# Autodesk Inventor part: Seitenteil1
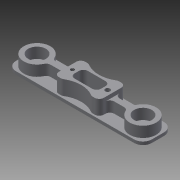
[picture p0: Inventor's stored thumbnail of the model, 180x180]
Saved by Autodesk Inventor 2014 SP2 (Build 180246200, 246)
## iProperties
Created: 2015-04
Part Number: Seitenteil1
Material: Generisch
Document SubType Name: Modeling
Designer: e_krauts
Density: 1 g/cm^3
Appearance: Vorgabe
Mass: 43.9559 g
Surface Area: 202.761 cm^2
Volume: 43.9559 cm^3
Author: e_krauts
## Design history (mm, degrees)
sketch "Skizze1"
  geometry: L1 (0, 0)-(154, 0); L2 (154, 0)-(154, 34); L3 (154, 34)-(0, 34); L4 (0, 34)-(0, 0)
  constraints: 8 end point, 2 parallel, 1 horizontal, 1 perpendicular
  dimensions: "d0" = 154 distance of L3.end L2.end; "d1" = 34 distance between parallel lines of L3 L1
extrude "Extrusion1" new body sketch "Skizze1" distance "d2" = 3.5; taper "d3" = 0 deg
sketch "Skizze2"
  geometry: L1 (0, 0)-(154, 0) reference; L2 (154, 0)-(154, 34) reference; L3 (154, 34)-(0, 34) reference; L4 (0, 34)-(0, 0) reference; L5 (77, 34)-(77, 0); L6 (0, 17)-(154, 17); L7 (77, 20)-(35.33, 20); L8 (77, 14)-(35.33, 14); L9 (77, 20)-(118.67, 20); L10 (77, 14)-(118.67, 14); L11 (154, 17)-(0, 17); A1 r 5 centre (35.33, 25) between (30.748, 23) and (35.33, 20); A2 r 15 centre (17, 17) between (30.748, 23) and (2, 17); A3 r 5 centre (35.33, 9) between (35.33, 14) and (30.748, 11); A4 r 15 centre (17, 17) between (2, 17) and (30.748, 11); A5 r 5 centre (118.67, 25) between (118.67, 20) and (123.252, 23); A6 r 15 centre (137, 17) between (123.252, 11) and (152, 17); A7 r 15 centre (137, 17) between (152, 17) and (123.252, 23); A8 r 5 centre (118.67, 9) between (123.252, 11) and (118.67, 14)
  constraints: 16 point on circle, 14 end point, 14 symmetric about line, 8 centre point, 5 point on line, 4 midpoint, 2 tangent, 1 parallel, 6 other
  dimensions: "d4" = 6 diameter of L7 L6; "d5" = 15 radius of A2; "d6" = 120 diameter of A2.centre L5; "d7" = 5 radius of A1
extrude "Extrusion2" join sketch "Skizze2" distance "d8" = 12; taper "d9" = 0 deg
sketch "Skizze3"
  geometry: A1 r 15 centre (17, 17) between (30.748, 23) and (30.748, 11) reference; A2 r 15 centre (137, 17) between (123.252, 11) and (123.252, 23) reference; 3 further points
  constraints: 2 coincident
hole "Bohrung1" sketch "Skizze3" at (17, 17), (137, 17) diameter "d10" = 20; stored, may be unused: countersink angle "d14" = 90 deg, drill point angle "d16" = 0 deg; dims "d11" = 6, "d12" = 4, "d13" = 2, "d15" = 12
fillet "Rundung1" dims "d17" = 10
sketch "Skizze4"
  geometry: L1 (144, 34)-(10, 34) reference; L2 (0, 24)-(0, 10) reference; L3 (10, 0)-(144, 0) reference; L4 (154, 10)-(154, 24) reference; L5 (77, 34)-(77, 0); L6 (0, 17)-(154, 17); L7 (102.5, 32)-(51.5, 32); L8 (51.5, 32)-(51.5, 2); L9 (51.5, 2)-(102.5, 2); L10 (102.5, 2)-(102.5, 32); L11 (102.5, 32)-(51.5, 2); L12 (51.5, 32)-(102.5, 2); 2 further points
  constraints: 16 end point, 7 midpoint, 2 parallel, 1 horizontal, 1 perpendicular
  dimensions: "d18" = 51 distance of L9.end L8.end; "d19" = 30 distance of L8.end L7.end
extrude "Extrusion3" join sketch "Skizze4" distance "d20" = 16.5; taper "d21" = 0 deg
fillet "Rundung2" dims "d22" = 5
sketch "Skizze5"
  geometry: L1 (62, 24.5)-(92, 24.5); L2 (92, 24.5)-(92, 9.5); L3 (92, 9.5)-(62, 9.5); L4 (62, 9.5)-(62, 24.5); L5 (62, 24.5)-(92, 9.5); L6 (92, 24.5)-(62, 9.5); 2 further points
  constraints: 12 end point, 2 midpoint, 2 parallel, 1 horizontal, 1 perpendicular
  dimensions: "d23" = 30 distance of L2.end L3.end; "d24" = 15 distance of L1.end L2.end
extrude "Extrusion4" cut sketch "Skizze5" distance "d25" = 16.5; taper "d26" = 0 deg
fillet "Rundung3" dims "d27" = 5
sketch "Skizze6"
  geometry: L1 (51.5, 27)-(51.5, 7) reference; L2 (56.5, 2)-(97.5, 2) reference; L3 (102.5, 7)-(102.5, 27) reference; L4 (97.5, 32)-(56.5, 32) reference; L5 (51.5, 17)-(102.5, 17); L6 (77, 32)-(77, 2); L7 (60.417, 32)-(93.583, 32); L8 (60.417, 2)-(93.583, 2); A1 r 30 centre (77, 57) between (60.417, 32) and (93.583, 32); A2 r 30 centre (77, -23) between (93.583, 2) and (60.417, 2); 1 further point
  constraints: 8 end point, 4 midpoint, 4 point on circle, 3 symmetric about line, 2 centre point, 2 point on line, 1 collinear, 1 other
  dimensions: "d30" = 80 diameter of A1.centre L5; "d31" = 30 radius of A1
extrude "Extrusion5" cut sketch "Skizze6" distance "d32" = 16.5; taper "d33" = 0 deg
fillet "Rundung4" dims "d34" = 5
sketch "Skizze7"
  geometry: L1 (51.5, 27)-(51.5, 7) reference; L2 (102.5, 7)-(102.5, 27) reference; L3 (51.5, 17)-(102.5, 17); L4 (77, 27)-(77, 7); A1 r 30 centre (77, -23) between (92.452, 2.714) and (61.548, 2.714) reference; A2 r 30 centre (77, 57) between (61.548, 31.286) and (92.452, 31.286) reference; 3 further points
  constraints: 4 end point, 2 midpoint, 2 point on circle, 1 point on line, 1 symmetric about line
hole "Bohrung2" sketch "Skizze7" diameter "d36" = 4.134; stored, may be unused: countersink angle "d40" = 90 deg, drill point angle "d42" = 118 deg; dims "d37" = 14, "d38" = 4, "d39" = 2, "d41" = 17
sketch "Skizze9"
  geometry: C1 r 5.2 at (0, 0) reference; 2 further points
  constraints: 1 coincident
hole "Bohrung4" sketch "Skizze9" diameter "d61" = 5.5; stored, may be unused: countersink angle "d65" = 90 deg, drill point angle "d67" = 118 deg; dims "d62" = 6, "d63" = 10.4, "d64" = 2, "d66" = 8
node "Volumenkörper1"
hole "Bohrung3" diameter "d54" = 10.4; stored, may be unused: countersink angle "d58" = 90 deg, drill point angle "d60" = 0 deg; dims "d52" = 17, "d53" = 57, "d55" = 6, "d56" = 4, "d57" = 2, "d59" = 0.5
